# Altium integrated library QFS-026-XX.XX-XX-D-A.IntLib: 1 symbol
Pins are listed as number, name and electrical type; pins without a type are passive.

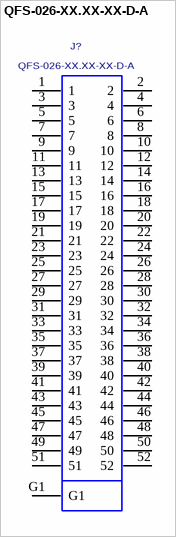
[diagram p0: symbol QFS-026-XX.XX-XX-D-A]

## QFS-026-XX.XX-XX-D-A
designator J?
0.635MM DOUBLE ROW TERMINAL STRIP.; MANUFACTURER: SAMTEC
footprint QFS-026-XX.XX-XX-D-A
pins: 1, 2, 3, 4, 5, 6, 7, 8, 9, 10, 11, 12, 13, 14, 15, 16, 17, 18, 19, 20, 21, 22, 23, 24, 25, 26, 27, 28, 29, 30, 31, 32, 33, 34, 35, 36, 37, 38, 39, 40, 41, 42, 43, 44, 45, 46, 47, 48, 49, 50, 51, 52, G1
